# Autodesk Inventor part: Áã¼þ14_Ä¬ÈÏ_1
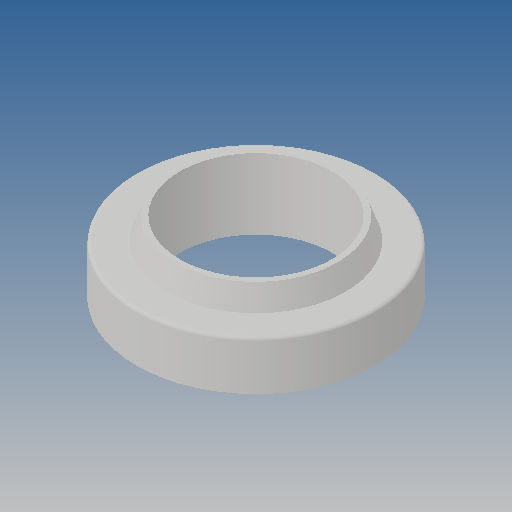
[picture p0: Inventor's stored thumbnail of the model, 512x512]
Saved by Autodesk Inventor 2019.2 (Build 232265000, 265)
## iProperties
Created: 2013-03
Part Number: Áã¼þ14_Ä¬ÈÏ_1
Material: Ogólny
Document SubType Name: Modeling
Designer: CADENGINEERING4
Density: 1 g/cm^3
Appearance: Domyślna
Author: CADENGINEERING4
Revision Number: ÈÎºÎ
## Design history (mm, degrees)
feature "NONE"
node "Bryła1"
